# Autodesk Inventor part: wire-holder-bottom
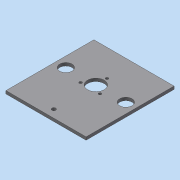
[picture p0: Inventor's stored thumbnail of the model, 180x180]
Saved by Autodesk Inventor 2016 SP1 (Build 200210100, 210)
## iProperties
Created: 2016-06
Part Number: wire-holder-bottom
Material: Generic
Document SubType Name: Modeling
Designer: Mohamed A.
Density: 1 g/cm^3
Appearance: Default
Author: Mohamed A.
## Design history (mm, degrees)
sketch "Sketch1"
  geometry: L1 (-41, 35)-(41, 35); L2 (41, 35)-(41, -35); L3 (41, -35)-(-41, -35); L4 (-41, -35)-(-41, 35); L5 (-41, 35)-(41, -35); L6 (41, 35)-(-41, -35); 1 further point
  constraints: 12 end point, 2 midpoint, 2 parallel, 1 horizontal, 1 perpendicular
  dimensions: "d0" = 82 distance of L2.end L3.end; "d1" = 70 distance of L1.end L2.end
extrude "Extrusion1" new body sketch "Sketch1" distance "d2" = 3; taper "d3" = 0 deg
sketch "Sketch2"
  geometry: C1 r 8.05 at (0, -4) reference; C2 r 2 at (9.922, -9.728) reference; C3 r 2 at (-9.922, -9.728) reference; C4 r 2 at (0, 7.457) reference; C5 r 1.4 at (-9.922, -9.728); C6 r 1.4 at (9.922, -9.728); C7 r 1.4 at (0, 7.457); C8 r 4.7 at (30.7, -4) reference; C9 r 4.7 at (-30.7, -4) reference; C10 r 6.3 at (30.7, -4); C11 r 6.3 at (-30.7, -4); C12 r 8.5 at (0, -4); 1 further point
  constraints: 6 centre point, 5 coincident
  dimensions: "d4" = 2.8 diameter of C5; "d5" = 2.8 diameter of C6; "d6" = 2.8 diameter of C7; "d9" = 12.6 diameter of C10; "d10" = 12.6 diameter of C11; "d20" = 17 diameter of C12
extrude "Extrusion2" cut sketch "Sketch2" distance "d7" = 3; taper "d8" = 0 deg
sketch "Sketch3"
  geometry: L1 (82, 0)-(0, 0) reference; L2 (82, 0)-(82, 3) reference; L3 (0, 3)-(82, 3) reference; L4 (0, 0)-(0, 3) reference; 1 further point
extrude "Extrusion3" join sketch "Sketch3" distance "d11" = 20; taper "d12" = 0 deg
sketch "Sketch4"
  geometry: L1 (0, -73)-(0, 53) reference; L2 (41, -55)-(-41, -55) reference; C1 r 2 at (0, -47); 1 further point
  constraints: 1 centre point, 1 point on line
  dimensions: "d13" = 4 diameter of C1; "d16" = 8 distance from line of C1.centre L2
extrude "Extrusion4" cut sketch "Sketch4" distance "d17" = 20; taper "d18" = 0 deg
body "Solid1"
node "Reference1"
node "Reference2"
node "Reference3"
node "Reference4"
node "Reference5"
node "Reference6"
node "Projected Loop1"
